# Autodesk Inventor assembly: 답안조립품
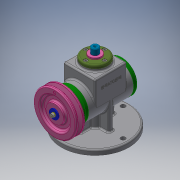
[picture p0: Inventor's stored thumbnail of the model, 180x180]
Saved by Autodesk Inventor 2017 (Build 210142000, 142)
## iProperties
Part Number: 답안조립품
Material: 일반
Document SubType Name: Assembly
Designer: 00-00
Author: 00-00
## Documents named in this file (18)
- C:\Users\00-00\Documents\Inventor\600906v1003\답안조립품.iam
- C:\Users\00-00\Documents\Inventor\600906v1003\600906V1003\V-벨트풀리.ipt
- C:\Users\00-00\Documents\Inventor\600906v1003\600906V1003\가이드부시.ipt
- C:\Users\00-00\Documents\Inventor\600906v1003\600906V1003\뒤커버.ipt
- C:\Users\00-00\Documents\Inventor\600906v1003\600906V1003\멈춤링.ipt
- C:\Users\00-00\Documents\Inventor\600906v1003\600906V1003\베어링 6203.ipt
- C:\Users\00-00\Documents\Inventor\600906v1003\600906V1003\본체.ipt
- C:\Users\00-00\Documents\Inventor\600906v1003\600906V1003\볼트 M4.ipt
- C:\Users\00-00\Documents\Inventor\600906v1003\600906V1003\상부커버.ipt
- C:\Users\00-00\Documents\Inventor\600906v1003\600906V1003\스프링와셔.ipt
- C:\Users\00-00\Documents\Inventor\600906v1003\600906V1003\스프링조립용 와셔.ipt
- C:\Users\00-00\Documents\Inventor\600906v1003\600906V1003\슬라이더.ipt
- C:\Users\00-00\Documents\Inventor\600906v1003\600906V1003\앞커버.ipt
- C:\Users\00-00\Documents\Inventor\600906v1003\600906V1003\오일 실 17 30 5.ipt
- C:\Users\00-00\Documents\Inventor\600906v1003\600906V1003\키 4x4x12.ipt
- C:\Users\00-00\Documents\Inventor\600906v1003\600906V1003\편심축.ipt
- C:\Users\00-00\Documents\Inventor\600906v1003\600906V1003\평와셔.ipt
- C:\Users\00-00\Documents\Inventor\600906v1003\가변스프링.ipt
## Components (3 placed, 3 different names)
1. V-벨트풀리:1
2. 가이드부시:1
3. 가변스프링:1
